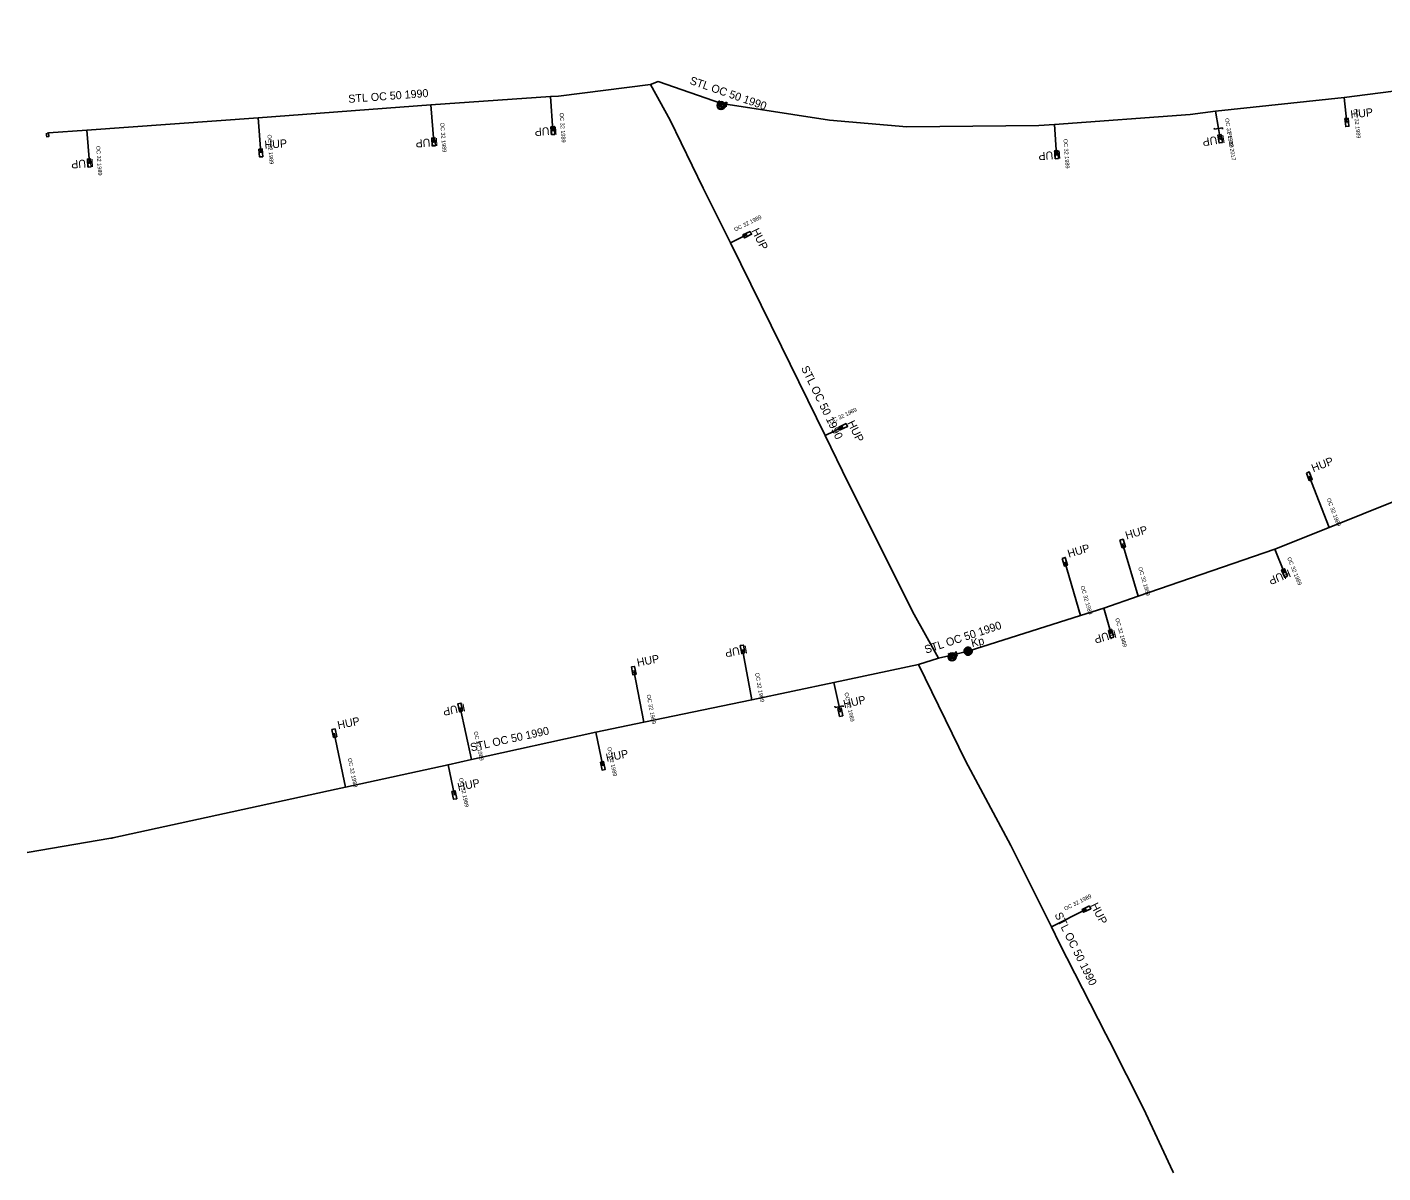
# Model space of a CAD drawing. Extents: x -744810 to -744454, y -1052534 to -1052253.
# Drawn here: x -744802.3 to -744632.9, y -1052533.5 to -1052390.4 of the extents above; entities that cross this region are included whole.
import ezdxf

# ---------------------------------------------------------------- set-up
doc = ezdxf.new("R2010")
doc.units = 0
for name, color, linetype in [('ST Kapák - provoz_popis', 7, 'Continuous'), ('ST Ochoz plynovodu - provoz', 7, 'Continuous'), ('ST Úsek p_ípojky - provoz', 7, 'Continuous'), ('ST Úsek plynovodu - provoz', 7, 'Continuous'), ('ST_HUP_22_23_popis', 7, 'Continuous'), ('Vrstva 1', 7, 'Continuous')]:
    doc.layers.add(name, color=color, linetype=linetype)

msp = doc.modelspace()

# ---------------------------------------------------------------- linework, layer by layer
at = {"layer": 'ST Ochoz plynovodu - provoz'}
for points in [[(-744715.58, -1052399.91), (-744715.62, -1052400.16), (-744715.65, -1052400.36), (-744715.35, -1052400.4), (-744715.28, -1052399.96)], [(-744799.92, -1052403.61), (-744799.9, -1052403.86), (-744799.89, -1052404.06), (-744799.64, -1052404.04), (-744799.67, -1052403.59)], [(-744686.8, -1052468.82), (-744686.75, -1052469.06), (-744686.7, -1052469.25), (-744686.41, -1052469.19), (-744686.51, -1052468.75)]]:
    msp.add_lwpolyline(points, dxfattribs=at)
at = {"layer": 'ST Úsek p_ípojky - provoz'}
for points in [[(-744736.94, -1052399.05), (-744736.64, -1052403.28)], [(-744637.76, -1052399.14), (-744637.41, -1052402.27)], [(-744751.89, -1052400.07), (-744751.53, -1052404.7)], [(-744653.82, -1052400.85), (-744653.46, -1052403.04)], [(-744773.47, -1052401.68), (-744773.14, -1052406.07)], [(-744673.97, -1052402.51), (-744673.69, -1052406.3)], [(-744653.46, -1052403.04), (-744653.3, -1052404.02), (-744653.25, -1052404.31)], [(-744794.86, -1052403.24), (-744794.56, -1052407.33)], [(-744714.46, -1052417.33), (-744712.34, -1052416.29)], [(-744702.63, -1052441.41), (-744700.36, -1052440.3)], [(-744639.65, -1052452.88), (-744642.12, -1052446.48)], [(-744663.48, -1052461.48), (-744665.44, -1052454.89)], [(-744646.43, -1052455.59), (-744645.2, -1052458.59)], [(-744670.69, -1052463.88), (-744672.66, -1052457.17)], [(-744667.78, -1052462.96), (-744666.88, -1052466.17)], [(-744711.77, -1052474.41), (-744712.94, -1052468.11)], [(-744725.28, -1052477.23), (-744726.54, -1052470.77)], [(-744701.51, -1052472.27), (-744700.87, -1052475.26)], [(-744746.81, -1052481.89), (-744748.21, -1052475.36)], [(-744700.87, -1052475.26), (-744700.74, -1052475.84), (-744700.72, -1052475.96)], [(-744762.55, -1052485.34), (-744763.95, -1052478.59)], [(-744731.25, -1052478.48), (-744730.4, -1052482.66)], [(-744749.74, -1052482.53), (-744748.95, -1052486.32)], [(-744674.34, -1052502.77), (-744669.96, -1052500.57)]]:
    msp.add_lwpolyline(points, dxfattribs=at)
at = {"layer": 'ST Úsek plynovodu - provoz'}
for points in [[(-744715.44, -1052399.93), (-744715.28, -1052399.96), (-744702.07, -1052401.99), (-744692.42, -1052402.83), (-744675.91, -1052402.65), (-744673.97, -1052402.51), (-744656.98, -1052401.26), (-744653.82, -1052400.85), (-744637.76, -1052399.14), (-744612.46, -1052395.89), (-744591.33, -1052393.93), (-744574.96, -1052392.24), (-744571.05, -1052391.86), (-744560.08, -1052390.36), (-744550.39, -1052405.27)], [(-744799.82, -1052403.6), (-744799.67, -1052403.59), (-744794.86, -1052403.24), (-744773.47, -1052401.68), (-744751.89, -1052400.07), (-744736.94, -1052399.05), (-744735.94, -1052398.98), (-744724.44, -1052397.52)], [(-744724.44, -1052397.52), (-744723.47, -1052397.16), (-744715.58, -1052399.91), (-744715.44, -1052399.93)], [(-744724.44, -1052397.52), (-744721.98, -1052401.97), (-744717.84, -1052410.48), (-744714.46, -1052417.33), (-744708.08, -1052430.27), (-744702.63, -1052441.41), (-744699.74, -1052447.32), (-744691.51, -1052463.74), (-744688.46, -1052469.2)], [(-744684.75, -1052468.34), (-744670.69, -1052463.88), (-744667.78, -1052462.96), (-744663.48, -1052461.48), (-744646.43, -1052455.59), (-744639.65, -1052452.88), (-744631.12, -1052449.48), (-744621.67, -1052445.69), (-744619.94, -1052443.28), (-744610.86, -1052439.31), (-744609.49, -1052438.71), (-744597.06, -1052432.68), (-744581.15, -1052424.33), (-744570.69, -1052418.53), (-744564.63, -1052414.91), (-744550.39, -1052405.27)], [(-744688.46, -1052469.2), (-744686.8, -1052468.82), (-744686.67, -1052468.79)], [(-744686.67, -1052468.79), (-744686.51, -1052468.75), (-744684.75, -1052468.34)], [(-744802.34, -1052493.5), (-744791.89, -1052491.71), (-744791.77, -1052491.69), (-744791.64, -1052491.67), (-744763.72, -1052485.6), (-744762.55, -1052485.34), (-744749.74, -1052482.53), (-744746.81, -1052481.89), (-744731.25, -1052478.48), (-744725.28, -1052477.23), (-744711.77, -1052474.41), (-744701.51, -1052472.27), (-744690.94, -1052470.02)], [(-744690.94, -1052470.02), (-744688.46, -1052469.2)], [(-744690.94, -1052470.02), (-744685.08, -1052482.04), (-744679.4, -1052492.61), (-744674.34, -1052502.77), (-744673.36, -1052504.77), (-744667.52, -1052516.18), (-744667.09, -1052517.09), (-744662.82, -1052525.49), (-744659.15, -1052533.36), (-744659.07, -1052533.53)]]:
    msp.add_lwpolyline(points, dxfattribs=at)
at = {"layer": 'Vrstva 1'}
for p, q in [((-744715.98, -1052400.15), (-744715.88, -1052399.56)), ((-744714.9, -1052399.72), (-744715.98, -1052400.15)), ((-744715.88, -1052399.56), (-744714.99, -1052400.31)), ((-744714.99, -1052400.31), (-744714.9, -1052399.72)), ((-744715.94, -1052400.39), (-744715.3, -1052399.92)), ((-744715.85, -1052399.84), (-744715.38, -1052400.48)), ((-744653.95, -1052403.12), (-744653.98, -1052402.97)), ((-744653.95, -1052403.12), (-744652.97, -1052402.96)), ((-744652.97, -1052402.96), (-744652.94, -1052403.1)), ((-744687.08, -1052469.2), (-744687.22, -1052468.62)), ((-744687.22, -1052468.62), (-744686.11, -1052468.96)), ((-744687.09, -1052468.85), (-744686.41, -1052469.27)), ((-744686.25, -1052468.38), (-744687.08, -1052469.2)), ((-744686.54, -1052468.72), (-744686.96, -1052469.4)), ((-744686.11, -1052468.96), (-744686.25, -1052468.38)), ((-744701.36, -1052475.36), (-744701.39, -1052475.22)), ((-744701.36, -1052475.36), (-744700.38, -1052475.15)), ((-744700.38, -1052475.15), (-744700.35, -1052475.3))]:
    msp.add_line(p, q, dxfattribs=at)
for points in [[(-744736.4, -1052403.76), (-744736.8, -1052403.79), (-744736.87, -1052402.8), (-744736.47, -1052402.77)], [(-744637.66, -1052401.79), (-744637.27, -1052401.75), (-744637.16, -1052402.74), (-744637.55, -1052402.79)], [(-744751.29, -1052405.18), (-744751.69, -1052405.21), (-744751.77, -1052404.22), (-744751.37, -1052404.18)], [(-744652.97, -1052404.77), (-744653.36, -1052404.83), (-744653.53, -1052403.85), (-744653.13, -1052403.78)], [(-744773.37, -1052405.59), (-744772.98, -1052405.56), (-744772.9, -1052406.55), (-744773.3, -1052406.58)], [(-744673.45, -1052406.78), (-744673.85, -1052406.81), (-744673.92, -1052405.81), (-744673.53, -1052405.78)], [(-744794.33, -1052407.81), (-744794.73, -1052407.84), (-744794.8, -1052406.84), (-744794.4, -1052406.82)], [(-744711.98, -1052415.89), (-744711.81, -1052416.25), (-744712.7, -1052416.69), (-744712.88, -1052416.33)], [(-744700, -1052439.9), (-744699.82, -1052440.26), (-744700.72, -1052440.7), (-744700.9, -1052440.34)], [(-744642.48, -1052446.08), (-744642.11, -1052445.94), (-744641.75, -1052446.87), (-744642.12, -1052447.02)], [(-744665.77, -1052454.47), (-744665.39, -1052454.35), (-744665.1, -1052455.31), (-744665.49, -1052455.42)], [(-744672.99, -1052456.74), (-744672.61, -1052456.63), (-744672.33, -1052457.59), (-744672.71, -1052457.7)], [(-744644.82, -1052458.97), (-744645.19, -1052459.13), (-744645.57, -1052458.2), (-744645.2, -1052458.05)], [(-744666.55, -1052466.6), (-744666.94, -1052466.7), (-744667.21, -1052465.74), (-744666.82, -1052465.63)], [(-744712.65, -1052468.56), (-744713.04, -1052468.64), (-744713.23, -1052467.65), (-744712.83, -1052467.58)], [(-744684.89, -1052467.86), (-744684.84, -1052467.85), (-744684.79, -1052467.84), (-744684.74, -1052467.84), (-744684.69, -1052467.84), (-744684.64, -1052467.85), (-744684.6, -1052467.86), (-744684.55, -1052467.88), (-744684.51, -1052467.9), (-744684.46, -1052467.93), (-744684.43, -1052467.96), (-744684.39, -1052467.99), (-744684.36, -1052468.03), (-744684.33, -1052468.07), (-744684.3, -1052468.11), (-744684.28, -1052468.16), (-744684.27, -1052468.2), (-744684.26, -1052468.25), (-744684.25, -1052468.3), (-744684.25, -1052468.35), (-744684.25, -1052468.4), (-744684.26, -1052468.45), (-744684.27, -1052468.49), (-744684.29, -1052468.54), (-744684.31, -1052468.58), (-744684.34, -1052468.62), (-744684.37, -1052468.66), (-744684.4, -1052468.7), (-744684.44, -1052468.73), (-744684.48, -1052468.76), (-744684.52, -1052468.79), (-744684.57, -1052468.8), (-744684.61, -1052468.82), (-744684.66, -1052468.83), (-744684.71, -1052468.84), (-744684.76, -1052468.84), (-744684.81, -1052468.84), (-744684.86, -1052468.83), (-744684.9, -1052468.82), (-744684.95, -1052468.8), (-744684.99, -1052468.78), (-744685.04, -1052468.75), (-744685.07, -1052468.72), (-744685.11, -1052468.69), (-744685.14, -1052468.65), (-744685.17, -1052468.61), (-744685.2, -1052468.57), (-744685.22, -1052468.52), (-744685.23, -1052468.48), (-744685.24, -1052468.43), (-744685.25, -1052468.38), (-744685.25, -1052468.33), (-744685.25, -1052468.28), (-744685.24, -1052468.23), (-744685.23, -1052468.19), (-744685.21, -1052468.14), (-744685.19, -1052468.1), (-744685.16, -1052468.05), (-744685.13, -1052468.01), (-744685.1, -1052467.98), (-744685.06, -1052467.95), (-744685.02, -1052467.92), (-744684.98, -1052467.89), (-744684.93, -1052467.87)], [(-744685.09, -1052468.43), (-744685.09, -1052468.4), (-744685.1, -1052468.37), (-744685.1, -1052468.33), (-744685.1, -1052468.3), (-744685.09, -1052468.26), (-744685.08, -1052468.23), (-744685.07, -1052468.2), (-744685.06, -1052468.17), (-744685.04, -1052468.14), (-744685.02, -1052468.11), (-744684.99, -1052468.09), (-744684.97, -1052468.06), (-744684.94, -1052468.04), (-744684.91, -1052468.03), (-744684.88, -1052468.01), (-744684.85, -1052468), (-744684.81, -1052467.99), (-744684.78, -1052467.99), (-744684.74, -1052467.99), (-744684.71, -1052467.99), (-744684.68, -1052468), (-744684.64, -1052468.01), (-744684.61, -1052468.02), (-744684.58, -1052468.03), (-744684.55, -1052468.05), (-744684.52, -1052468.07), (-744684.5, -1052468.1), (-744684.47, -1052468.12), (-744684.46, -1052468.15), (-744684.44, -1052468.18), (-744684.42, -1052468.21), (-744684.41, -1052468.24), (-744684.41, -1052468.28), (-744684.4, -1052468.31), (-744684.4, -1052468.35), (-744684.4, -1052468.38), (-744684.41, -1052468.41), (-744684.42, -1052468.45), (-744684.43, -1052468.48), (-744684.44, -1052468.51), (-744684.46, -1052468.54), (-744684.48, -1052468.57), (-744684.51, -1052468.59), (-744684.53, -1052468.61), (-744684.56, -1052468.63), (-744684.59, -1052468.65), (-744684.62, -1052468.67), (-744684.65, -1052468.68), (-744684.69, -1052468.68), (-744684.72, -1052468.69), (-744684.76, -1052468.69), (-744684.79, -1052468.69), (-744684.82, -1052468.68), (-744684.86, -1052468.67), (-744684.89, -1052468.66), (-744684.92, -1052468.65), (-744684.95, -1052468.63), (-744684.98, -1052468.61), (-744685, -1052468.58), (-744685.03, -1052468.56), (-744685.04, -1052468.53), (-744685.06, -1052468.5), (-744685.08, -1052468.47)], [(-744684.46, -1052468.26), (-744684.45, -1052468.29), (-744684.45, -1052468.32), (-744684.45, -1052468.34), (-744684.45, -1052468.37), (-744684.46, -1052468.4), (-744684.46, -1052468.43), (-744684.47, -1052468.46), (-744684.49, -1052468.49), (-744684.5, -1052468.51), (-744684.52, -1052468.53), (-744684.54, -1052468.56), (-744684.56, -1052468.58), (-744684.59, -1052468.59), (-744684.61, -1052468.61), (-744684.64, -1052468.62), (-744684.67, -1052468.63), (-744684.7, -1052468.63), (-744684.73, -1052468.64), (-744684.76, -1052468.64), (-744684.78, -1052468.64), (-744684.81, -1052468.63), (-744684.84, -1052468.63), (-744684.87, -1052468.61), (-744684.9, -1052468.6), (-744684.92, -1052468.59), (-744684.95, -1052468.57), (-744684.97, -1052468.55), (-744684.99, -1052468.52), (-744685, -1052468.5), (-744685.02, -1052468.48), (-744685.03, -1052468.45), (-744685.04, -1052468.42), (-744685.05, -1052468.39), (-744685.05, -1052468.36), (-744685.05, -1052468.33), (-744685.05, -1052468.3), (-744685.04, -1052468.28), (-744685.04, -1052468.25), (-744685.03, -1052468.22), (-744685.01, -1052468.19), (-744685, -1052468.17), (-744684.98, -1052468.14), (-744684.96, -1052468.12), (-744684.94, -1052468.1), (-744684.91, -1052468.09), (-744684.89, -1052468.07), (-744684.86, -1052468.06), (-744684.83, -1052468.05), (-744684.8, -1052468.04), (-744684.77, -1052468.04), (-744684.74, -1052468.04), (-744684.72, -1052468.04), (-744684.69, -1052468.05), (-744684.66, -1052468.05), (-744684.63, -1052468.06), (-744684.6, -1052468.08), (-744684.58, -1052468.09), (-744684.56, -1052468.11), (-744684.53, -1052468.13), (-744684.51, -1052468.15), (-744684.5, -1052468.18), (-744684.48, -1052468.2), (-744684.47, -1052468.23)], [(-744684.61, -1052468.3), (-744684.6, -1052468.31), (-744684.6, -1052468.33), (-744684.6, -1052468.34), (-744684.6, -1052468.36), (-744684.6, -1052468.37), (-744684.61, -1052468.39), (-744684.61, -1052468.4), (-744684.62, -1052468.41), (-744684.63, -1052468.42), (-744684.64, -1052468.44), (-744684.65, -1052468.45), (-744684.66, -1052468.46), (-744684.67, -1052468.47), (-744684.68, -1052468.47), (-744684.7, -1052468.48), (-744684.71, -1052468.48), (-744684.72, -1052468.49), (-744684.74, -1052468.49), (-744684.75, -1052468.49), (-744684.77, -1052468.49), (-744684.78, -1052468.49), (-744684.8, -1052468.48), (-744684.81, -1052468.48), (-744684.82, -1052468.47), (-744684.84, -1052468.46), (-744684.85, -1052468.45), (-744684.86, -1052468.44), (-744684.87, -1052468.43), (-744684.88, -1052468.42), (-744684.88, -1052468.41), (-744684.89, -1052468.39), (-744684.89, -1052468.38), (-744684.9, -1052468.37), (-744684.9, -1052468.35), (-744684.9, -1052468.34), (-744684.9, -1052468.32), (-744684.9, -1052468.31), (-744684.89, -1052468.29), (-744684.89, -1052468.28), (-744684.88, -1052468.27), (-744684.87, -1052468.25), (-744684.86, -1052468.24), (-744684.85, -1052468.23), (-744684.84, -1052468.22), (-744684.83, -1052468.21), (-744684.82, -1052468.21), (-744684.8, -1052468.2), (-744684.79, -1052468.19), (-744684.78, -1052468.19), (-744684.76, -1052468.19), (-744684.75, -1052468.19), (-744684.73, -1052468.19), (-744684.72, -1052468.19), (-744684.7, -1052468.2), (-744684.69, -1052468.2), (-744684.68, -1052468.21), (-744684.66, -1052468.22), (-744684.65, -1052468.22), (-744684.64, -1052468.23), (-744684.63, -1052468.25), (-744684.62, -1052468.26), (-744684.62, -1052468.27), (-744684.61, -1052468.28)], [(-744726.83, -1052470.31), (-744726.44, -1052470.24), (-744726.25, -1052471.22), (-744726.64, -1052471.3)], [(-744747.91, -1052475.81), (-744748.3, -1052475.89), (-744748.51, -1052474.91), (-744748.12, -1052474.83)], [(-744701.02, -1052475.52), (-744700.63, -1052475.43), (-744700.41, -1052476.4), (-744700.8, -1052476.49)], [(-744764.25, -1052478.14), (-744763.85, -1052478.06), (-744763.65, -1052479.04), (-744764.04, -1052479.12)], [(-744730.69, -1052482.21), (-744730.3, -1052482.13), (-744730.1, -1052483.11), (-744730.49, -1052483.19)], [(-744749.25, -1052485.87), (-744748.85, -1052485.79), (-744748.65, -1052486.77), (-744749.04, -1052486.85)], [(-744669.6, -1052500.17), (-744669.42, -1052500.52), (-744670.32, -1052500.97), (-744670.5, -1052500.62)]]:
    msp.add_lwpolyline(points, close=True, dxfattribs=at)
for centre, radius in [((-744715.62, -1052400.16), 0.5), ((-744715.62, -1052400.16), 0.4), ((-744686.75, -1052469.06), 0.5), ((-744686.75, -1052469.06), 0.4)]:
    msp.add_circle(centre, radius, dxfattribs=at)

# ---------------------------------------------------------------- texts
at = {"layer": 'ST Kapák - provoz_popis'}
msp.add_text('Kp', height=1, rotation=13, dxfattribs=at).set_placement((-744684.25, -1052467.84))
at = {"layer": 'ST Úsek p_ípojky - provoz'}
for s, rotation, p in [('OC 32 1989', 274.0972, (-744735.79, -1052401.09)), ('OC 32 1989', 276.3844, (-744636.59, -1052400.59)), ('OC 32 1989', 274.4716, (-744750.71, -1052402.31)), ('OC 32 1989', 279.3689, (-744652.65, -1052401.78)), ('OC 32 1989', 274.3388, (-744772.31, -1052403.8)), ('OC 32 1989', 274.2113, (-744672.83, -1052404.33)), ('PE 32 2017', 279.3869, (-744652.37, -1052403.51)), ('OC 32 1989', 274.1961, (-744793.72, -1052405.21)), ('OC 32 1989', 26.2502, (-744713.84, -1052415.91)), ('OC 32 1989', 26.0884, (-744701.94, -1052439.96)), ('OC 32 1989', 291.0789, (-744639.95, -1052449.32)), ('OC 32 1989', 292.3398, (-744644.89, -1052456.71)), ('OC 32 1989', 286.5428, (-744663.5, -1052457.9)), ('OC 32 1989', 286.3415, (-744670.71, -1052460.24)), ('OC 32 1989', 285.6667, (-744666.37, -1052464.29)), ('OC 32 1989', 280.5016, (-744711.37, -1052471.08)), ('OC 32 1989', 281.0232, (-744724.93, -1052473.81)), ('OC 32 1989', 282.1118, (-744700.21, -1052473.55)), ('OC 32 1989', 282.0906, (-744746.53, -1052478.42)), ('OC 32 1989', 281.5287, (-744729.84, -1052480.37)), ('OC 32 1989', 281.6995, (-744762.27, -1052481.76)), ('OC 32 1989', 281.8094, (-744748.37, -1052484.22)), ('OC 32 1989', 26.6696, (-744672.6, -1052500.78))]:
    msp.add_text(s, height=0.5, rotation=rotation, dxfattribs=at).set_placement(p)
at = {"layer": 'ST Úsek plynovodu - provoz'}
for rotation, p in [(340.7844, (-744719.62, -1052397.44)), (4.2667, (-744762.17, -1052399.83)), (296.0692, (-744705.65, -1052432.97)), (18.2962, (-744690.01, -1052468.66)), (12.361, (-744746.84, -1052480.87)), (296.4748, (-744673.97, -1052501.26))]:
    msp.add_text('STL OC 50 1990', height=1, rotation=rotation, dxfattribs=at).set_placement(p)
at = {"layer": 'ST_HUP_22_23_popis'}
for rotation, p in [(6.38, (-744636.91, -1052401.77)), (184.1, (-744736.14, -1052402.78)), (4.34, (-744772.64, -1052405.57)), (184.47, (-744751.03, -1052404.2)), (189.37, (-744652.75, -1052403.81)), (184.21, (-744673.19, -1052405.8)), (184.2, (-744794.06, -1052406.83)), (296.25, (-744711.84, -1052415.79)), (296.09, (-744699.86, -1052439.8)), (21.08, (-744641.62, -1052445.98)), (16.54, (-744664.94, -1052454.39)), (16.34, (-744672.16, -1052456.67)), (202.34, (-744644.7, -1052458.09)), (195.67, (-744666.38, -1052465.67)), (11.02, (-744726.04, -1052470.27)), (190.5, (-744712.44, -1052467.61)), (12.63, (-744700.22, -1052475.46)), (192.09, (-744747.71, -1052474.86)), (11.7, (-744763.45, -1052478.09)), (11.53, (-744729.9, -1052482.16)), (11.81, (-744748.45, -1052485.82)), (296.67, (-744669.46, -1052500.07))]:
    msp.add_text('HUP', height=1, rotation=rotation, dxfattribs=at).set_placement(p)

doc.saveas('drawing.dxf')
